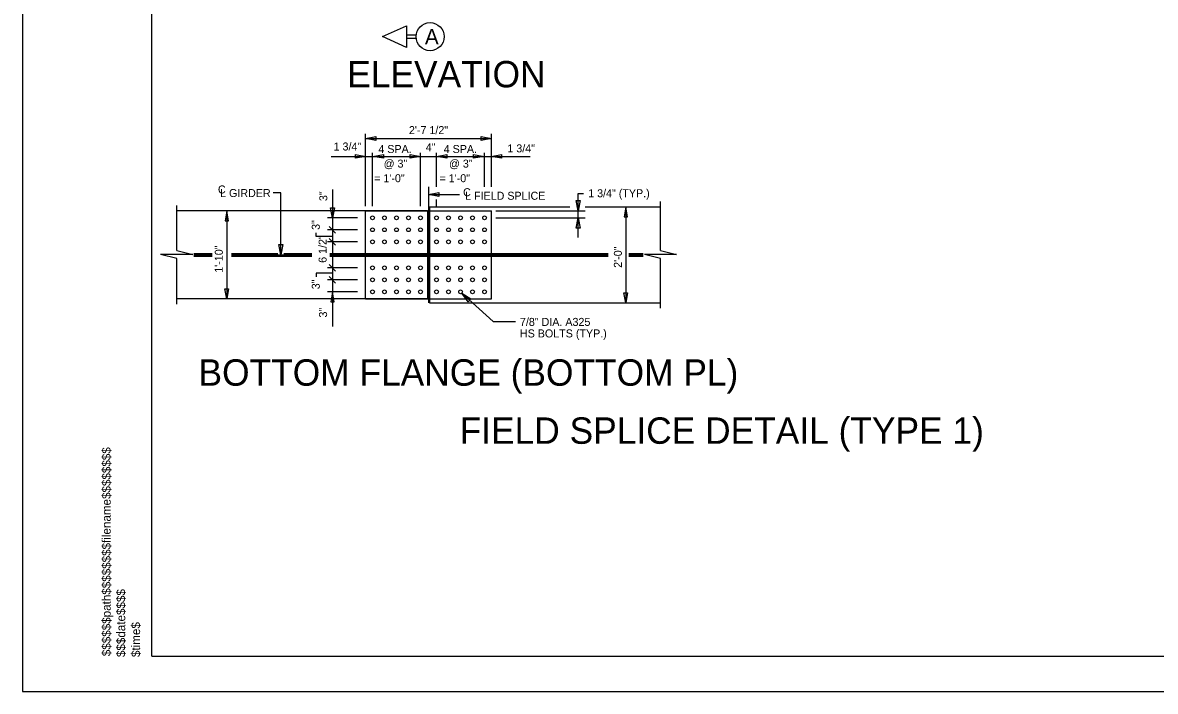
# Model space of a CAD drawing. Extents: x 1970675.2 to 1970715, y 796143 to 796167.2.
# Drawn here: x 1970675.24 to 1970692.92, y 796143.05 to 796153.49 of the extents above; entities that cross this region are included whole.
import ezdxf

# ---------------------------------------------------------------- set-up
doc = ezdxf.new("R2010")
doc.units = 0
for name, color, linetype in [('BR_AUTO DIMENSION', 7, 'Continuous'), ('BR_BORDER LINES', 7, 'Continuous'), ('BR_CENTER LINES', 7, 'Continuous'), ('BR_STRUCTURAL STEEL', 7, 'Continuous'), ('BR_TEXT', 7, 'Continuous'), ('Default', 7, 'Continuous'), ('Level 31', 7, 'Continuous'), ('RD_SHT_ID', 7, 'Continuous')]:
    doc.layers.add(name, color=color, linetype=linetype)

msp = doc.modelspace()

# ---------------------------------------------------------------- linework, layer by layer
at = {"layer": 'BR_AUTO DIMENSION'}
for p, q in [((1970680.588, 796150.622), (1970680.588, 796151.754)), ((1970680.588, 796151.681), (1970682.557, 796151.681)), ((1970682.557, 796150.923), (1970682.557, 796151.752)), ((1970680.698, 796150.622), (1970680.698, 796151.457)), ((1970681.448, 796150.622), (1970681.448, 796151.457)), ((1970681.698, 796150.925), (1970681.698, 796151.457)), ((1970682.448, 796150.925), (1970682.448, 796151.457)), ((1970680.053, 796151.401), (1970683.16, 796151.401)), ((1970679.266, 796150.833), (1970679.15, 796150.833)), ((1970679.266, 796149.863), (1970679.266, 796150.833)), ((1970680.073, 796150.883), (1970680.073, 796148.742)), ((1970681.698, 796150.622), (1970681.698, 796150.729)), ((1970683.908, 796150.135), (1970683.908, 796150.822)), ((1970683.908, 796150.822), (1970683.995, 796150.822)), ((1970678.422, 796150.551), (1970678.422, 796149.176)), ((1970682.624, 796150.551), (1970684.018, 796150.551)), ((1970684.652, 796150.613), (1970684.652, 796149.113)), ((1970680.466, 796150.441), (1970679.998, 796150.441)), ((1970682.624, 796150.441), (1970684.018, 796150.441)), ((1970680.466, 796150.254), (1970679.998, 796150.254)), ((1970680.123, 796150.203), (1970680.024, 796150.304)), ((1970680.466, 796150.066), (1970679.998, 796150.066)), ((1970680.123, 796150.016), (1970680.024, 796150.117)), ((1970680.466, 796149.66), (1970679.998, 796149.66)), ((1970680.123, 796149.609), (1970680.024, 796149.71)), ((1970680.123, 796149.422), (1970680.024, 796149.523)), ((1970680.466, 796149.472), (1970679.998, 796149.472)), ((1970680.466, 796149.285), (1970679.998, 796149.285)), ((1970682.582, 796148.822), (1970682.091, 796149.262)), ((1970682.582, 796148.822), (1970682.93, 796148.822))]:
    msp.add_line(p, q, dxfattribs=at)
for points in [[(1970680.751, 796151.65), (1970680.588, 796151.681), (1970680.751, 796151.712)], [(1970682.395, 796151.712), (1970682.557, 796151.681), (1970682.395, 796151.65)], [(1970680.434, 796151.432), (1970680.596, 796151.401), (1970680.434, 796151.37)], [(1970680.868, 796151.37), (1970680.705, 796151.401), (1970680.868, 796151.432)], [(1970681.285, 796151.432), (1970681.448, 796151.401), (1970681.285, 796151.37)], [(1970681.86, 796151.37), (1970681.698, 796151.401), (1970681.86, 796151.432)], [(1970682.277, 796151.432), (1970682.44, 796151.401), (1970682.277, 796151.37)], [(1970682.712, 796151.37), (1970682.549, 796151.401), (1970682.712, 796151.432)], [(1970681.735, 796150.776), (1970681.573, 796150.807), (1970681.735, 796150.838)], [(1970683.939, 796150.713), (1970683.908, 796150.551), (1970683.877, 796150.713)], [(1970678.396, 796150.394), (1970678.448, 796150.394), (1970678.422, 796150.551)], [(1970680.103, 796150.597), (1970680.073, 796150.441), (1970680.043, 796150.597)], [(1970684.626, 796150.457), (1970684.678, 796150.457), (1970684.652, 796150.613)], [(1970683.877, 796150.279), (1970683.908, 796150.441), (1970683.939, 796150.279)], [(1970679.297, 796150.026), (1970679.266, 796149.863), (1970679.235, 796150.026)], [(1970678.452, 796149.332), (1970678.422, 796149.176), (1970678.392, 796149.332)], [(1970680.047, 796149.129), (1970680.099, 796149.129), (1970680.073, 796149.285)], [(1970682.191, 796149.13), (1970682.091, 796149.262), (1970682.233, 796149.177)], [(1970684.682, 796149.269), (1970684.652, 796149.113), (1970684.622, 796149.269)]]:
    msp.add_lwpolyline(points, close=True, dxfattribs=at)
for points in [[(1970681.573, 796150.807), (1970682.058, 796150.807)], [(1970680.073, 796150.148), (1970679.82, 796150.148), (1970679.82, 796150.209)], [(1970680.073, 796149.578), (1970679.82, 796149.578), (1970679.82, 796149.517)]]:
    msp.add_lwpolyline(points, dxfattribs=at)
at = {"layer": 'BR_BORDER LINES'}
for q in [(1970677.253, 796166.696), (1970714.286, 796143.596)]:
    msp.add_line((1970677.253, 796143.596), q, dxfattribs=at)
at = {"layer": 'BR_CENTER LINES'}
for p, q in [((1970681.573, 796150.927), (1970681.573, 796149.113)), ((1970677.911, 796149.863), (1970678.196, 796149.863)), ((1970678.495, 796149.863), (1970679.266, 796149.863)), ((1970679.266, 796149.863), (1970679.751, 796149.863)), ((1970680.03, 796149.863), (1970684.377, 796149.863)), ((1970684.7, 796149.863), (1970684.924, 796149.863)), ((1970684.7, 796149.863), (1970684.74, 796149.863))]:
    msp.add_line(p, q, dxfattribs=at)
at = {"layer": 'BR_STRUCTURAL STEEL'}
for p, q in [((1970681.557, 796150.551), (1970677.643, 796150.551)), ((1970680.588, 796149.176), (1970680.588, 796150.551)), ((1970680.588, 796150.551), (1970682.557, 796150.551)), ((1970681.557, 796150.551), (1970681.557, 796149.176)), ((1970681.588, 796150.613), (1970683.778, 796150.613)), ((1970681.588, 796150.613), (1970681.588, 796150.551)), ((1970681.588, 796150.551), (1970681.588, 796149.176)), ((1970682.557, 796149.176), (1970682.557, 796150.551)), ((1970684.019, 796150.613), (1970685.195, 796150.613)), ((1970677.911, 796149.883), (1970678.196, 796149.883)), ((1970677.911, 796149.844), (1970678.196, 796149.844)), ((1970678.495, 796149.883), (1970679.221, 796149.883)), ((1970678.495, 796149.844), (1970679.752, 796149.844)), ((1970679.316, 796149.883), (1970679.752, 796149.883)), ((1970680.032, 796149.883), (1970681.557, 796149.883)), ((1970680.032, 796149.844), (1970681.557, 796149.844)), ((1970681.588, 796149.883), (1970684.376, 796149.883)), ((1970681.588, 796149.844), (1970684.377, 796149.844)), ((1970684.7, 796149.883), (1970684.924, 796149.883)), ((1970684.7, 796149.844), (1970684.924, 796149.844)), ((1970684.702, 796149.847), (1970684.74, 796149.847)), ((1970681.557, 796149.176), (1970677.643, 796149.176)), ((1970680.588, 796149.176), (1970682.557, 796149.176)), ((1970681.588, 796149.176), (1970681.588, 796149.113)), ((1970681.588, 796149.113), (1970685.195, 796149.113))]:
    msp.add_line(p, q, dxfattribs=at)
for centre in [(1970680.698, 796150.441), (1970680.698, 796150.441), (1970680.885, 796150.441), (1970680.885, 796150.441), (1970681.073, 796150.441), (1970681.073, 796150.441), (1970681.26, 796150.441), (1970681.26, 796150.441), (1970681.448, 796150.441), (1970681.448, 796150.441), (1970681.698, 796150.441), (1970681.698, 796150.441), (1970681.885, 796150.441), (1970681.885, 796150.441), (1970682.073, 796150.441), (1970682.073, 796150.441), (1970682.26, 796150.441), (1970682.26, 796150.441), (1970682.448, 796150.441), (1970682.448, 796150.441), (1970680.698, 796150.254), (1970680.698, 796150.254), (1970680.885, 796150.254), (1970680.885, 796150.254), (1970681.073, 796150.254), (1970681.073, 796150.254), (1970681.26, 796150.254), (1970681.26, 796150.254), (1970681.448, 796150.254), (1970681.448, 796150.254), (1970681.698, 796150.254), (1970681.698, 796150.254), (1970681.885, 796150.254), (1970681.885, 796150.254), (1970682.073, 796150.254), (1970682.073, 796150.254), (1970682.26, 796150.254), (1970682.26, 796150.254), (1970682.448, 796150.254), (1970682.448, 796150.254), (1970680.698, 796150.066), (1970680.698, 796150.066), (1970680.885, 796150.066), (1970680.885, 796150.066), (1970681.073, 796150.066), (1970681.073, 796150.066), (1970681.26, 796150.066), (1970681.26, 796150.066), (1970681.448, 796150.066), (1970681.448, 796150.066), (1970681.698, 796150.066), (1970681.698, 796150.066), (1970681.885, 796150.066), (1970681.885, 796150.066), (1970682.073, 796150.066), (1970682.073, 796150.066), (1970682.26, 796150.066), (1970682.26, 796150.066), (1970682.448, 796150.066), (1970682.448, 796150.066), (1970680.698, 796149.66), (1970680.698, 796149.66), (1970680.885, 796149.66), (1970680.885, 796149.66), (1970681.073, 796149.66), (1970681.073, 796149.66), (1970681.26, 796149.66), (1970681.26, 796149.66), (1970681.448, 796149.66), (1970681.448, 796149.66), (1970681.698, 796149.66), (1970681.698, 796149.66), (1970681.885, 796149.66), (1970681.885, 796149.66), (1970682.073, 796149.66), (1970682.073, 796149.66), (1970682.26, 796149.66), (1970682.26, 796149.66), (1970682.448, 796149.66), (1970682.448, 796149.66), (1970680.698, 796149.472), (1970680.698, 796149.472), (1970680.885, 796149.472), (1970680.885, 796149.472), (1970681.073, 796149.472), (1970681.073, 796149.472), (1970681.26, 796149.472), (1970681.26, 796149.472), (1970681.448, 796149.472), (1970681.448, 796149.472), (1970681.698, 796149.472), (1970681.698, 796149.472), (1970681.885, 796149.472), (1970681.885, 796149.472), (1970682.073, 796149.472), (1970682.073, 796149.472), (1970682.26, 796149.472), (1970682.26, 796149.472), (1970682.448, 796149.472), (1970682.448, 796149.472), (1970680.698, 796149.285), (1970680.698, 796149.285), (1970680.885, 796149.285), (1970680.885, 796149.285), (1970681.073, 796149.285), (1970681.073, 796149.285), (1970681.26, 796149.285), (1970681.26, 796149.285), (1970681.448, 796149.285), (1970681.448, 796149.285), (1970681.698, 796149.285), (1970681.698, 796149.285), (1970681.885, 796149.285), (1970681.885, 796149.285), (1970682.073, 796149.285), (1970682.073, 796149.285), (1970682.26, 796149.285), (1970682.26, 796149.285), (1970682.448, 796149.285), (1970682.448, 796149.285)]:
    msp.add_circle(centre, 0.0293, dxfattribs=at)
at = {"layer": 'BR_TEXT'}
for points in [[(1970681.229, 796153.101), (1970680.853, 796153.27), (1970681.229, 796153.439)], [(1970681.379, 796153.295), (1970681.229, 796153.295), (1970681.229, 796153.245), (1970681.379, 796153.245)]]:
    msp.add_lwpolyline(points, close=True, dxfattribs=at)
msp.add_circle((1970681.598, 796153.27), 0.219, dxfattribs=at)
at = {"layer": 'Default'}
for p, q in [((1970677.643, 796149.929), (1970677.643, 796150.634)), ((1970685.195, 796149.929), (1970685.195, 796150.696)), ((1970677.895, 796149.868), (1970677.391, 796149.868)), ((1970677.643, 796149.808), (1970677.391, 796149.868)), ((1970677.643, 796149.929), (1970677.895, 796149.868)), ((1970685.447, 796149.868), (1970684.944, 796149.868)), ((1970685.195, 796149.808), (1970684.944, 796149.868)), ((1970685.195, 796149.929), (1970685.447, 796149.868)), ((1970677.643, 796149.092), (1970677.643, 796149.808)), ((1970685.195, 796149.03), (1970685.195, 796149.808))]:
    msp.add_line(p, q, dxfattribs=at)
at = {"layer": 'Level 31'}
msp.add_lwpolyline([(1970675.236, 796167.246), (1970675.236, 796143.046), (1970714.836, 796143.046), (1970714.836, 796167.246)], dxfattribs=at)

# ---------------------------------------------------------------- texts
at = {"layer": 'BR_TEXT'}
for s, height, p in [('A', 0.24, (1970681.517, 796153.15)), ('ELEVATION', 0.4125, (1970680.304, 796152.478)), ('2\'-7 1/2"', 0.125, (1970681.267, 796151.748)), ('1 3/4"', 0.125, (1970680.091, 796151.492)), ('4"', 0.125, (1970681.53, 796151.48)), ('4 SPA. ', 0.125, (1970680.79, 796151.453)), ('4 SPA. ', 0.125, (1970681.81, 796151.453)), ('1 3/4"', 0.125, (1970682.804, 796151.463)), ('@ 3" ', 0.125, (1970680.873, 796151.225)), ('@ 3" ', 0.125, (1970681.893, 796151.225)), ('= 1\'-0"', 0.125, (1970680.724, 796150.997)), ('= 1\'-0"', 0.125, (1970681.744, 796150.997)), ('C', 0.125, (1970678.285, 796150.821)), ('L GIRDER', 0.125, (1970678.319, 796150.765)), ('C', 0.125, (1970682.113, 796150.778)), ('1 3/4" (TYP.)', 0.125, (1970684.066, 796150.762)), ('L FIELD SPLICE', 0.125, (1970682.144, 796150.723)), ('7/8" DIA. A325', 0.125, (1970683, 796148.753)), ('HS BOLTS (TYP.)', 0.125, (1970683, 796148.573)), ('BOTTOM FLANGE (BOTTOM PL)', 0.4125, (1970677.982, 796147.819)), ('FIELD SPLICE DETAIL (TYPE 1)', 0.4125, (1970682.059, 796146.912))]:
    msp.add_text(s, height=height, dxfattribs=at).set_placement(p)
for s, p in [('3"', (1970679.993, 796150.702)), ('3"', (1970679.875, 796150.252)), ('6 1/2"', (1970679.982, 796149.738)), ('1\'-10"', (1970678.361, 796149.583)), ('2\'-0"', (1970684.592, 796149.66)), ('3"', (1970679.875, 796149.325)), ('3"', (1970679.989, 796148.884))]:
    msp.add_text(s, height=0.125, rotation=90, dxfattribs=at).set_placement(p)
at = {"layer": 'RD_SHT_ID'}
for s, height, p in [('$$$$$$path$$$$$$$$filename$$$$$$$$', 0.13582, (1970676.611, 796143.596)), ('$$$date$$$$', 0.13582, (1970676.838, 796143.582)), ('$time$', 0.1358, (1970677.07, 796143.582))]:
    msp.add_text(s, height=height, rotation=90, dxfattribs=at).set_placement(p)

doc.saveas('drawing.dxf')
